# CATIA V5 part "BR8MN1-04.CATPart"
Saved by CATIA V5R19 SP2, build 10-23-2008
Part number: BR8MN1-04
Definition: design
Nomenclature: BR8MN1-04
Source: Unknown
Bounding box of the stored display mesh (mm): x -4.6 to 7.9, y 0 to 12, z 0 to 20.32
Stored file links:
  Z:\fausse table rondelle-20220905T211342Z-001\fausse table rondelle\BR8MN1-04.CATPart
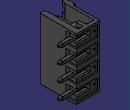
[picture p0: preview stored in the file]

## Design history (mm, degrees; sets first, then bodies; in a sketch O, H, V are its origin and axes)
AxisSystem1: origin (0, 0, 0), X (1, 0, 0), Y (0, 1, 0), Z (0, 0, 1)
Body1 "MANIFOLD_SOLID_BREP #177283" (main body)
  Solid1: solid without history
